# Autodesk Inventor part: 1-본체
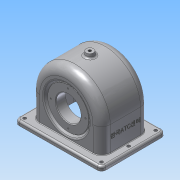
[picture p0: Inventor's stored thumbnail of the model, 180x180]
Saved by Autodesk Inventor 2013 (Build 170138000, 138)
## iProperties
Created: 2015-09
Part Number: 1-본체
Material: 알루미늄 6061
Document SubType Name: Modeling
Designer: Administrator
Mass: 724.051 g
Surface Area: 888.547 cm^2
Volume: 267.177 cm^3
Density: 2.71 g/cm^3
Author: Administrator
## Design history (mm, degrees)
sketch "스케치1"
  geometry: L1 (-45, 70)-(45, 70); L2 (52, 63)-(52, -63); L3 (45, -70)-(-45, -70); L4 (-52, -63)-(-52, 63); A1 r 7 centre (-45, 63) between (-45, 70) and (-52, 63); A2 r 7 centre (45, 63) between (52, 63) and (45, 70); A3 r 7 centre (45, -63) between (45, -70) and (52, -63); A4 r 7 centre (-45, -63) between (-52, -63) and (-45, -70); 6 further points
  constraints: 8 end point, 8 point on circle, 8 tangent, 6 point on line, 4 centre point, 3 equal radius, 2 midpoint, 2 parallel, 1 horizontal, 1 horizontal alignment, 1 perpendicular, 1 vertical alignment
  dimensions: "d0" = 104 distance of point (-52, 70) point (52, 70); "d2" = 140 distance of point (52, 70) point (52, -70); "d3" = 7 radius of A1
extrude "돌출1" new body sketch "스케치1" distance "d4" = 7; taper "d5" = 0 deg
sketch "스케치2"
  geometry: L1 (-63, 0)-(63, 0) reference; L2 (-63, 0)-(-63, 7) reference; L3 (63, 7)-(-63, 7) reference; L4 (63, 0)-(63, 7) reference; L5 (-57, 7)-(-57, 47); L6 (57, 47)-(57, 7); A1 r 57 centre (0, 47) between (57, 47) and (-57, 47); 2 further points
  constraints: 4 end point, 2 point on circle, 2 point on line, 2 tangent, 1 centre point, 1 midpoint, 1 parallel, 1 perpendicular, 1 vertical alignment
  dimensions: "d6" = 57 radius of A1; "d8" = 40 distance from line of A1.centre L3
extrude "돌출2" join sketch "스케치2" stored distance "d9" = 77; taper "d10" = 0 deg
sketch "스케치3"
  geometry: C1 r 31 at (-47, 0); A1 r 57 centre (-47, 0) between (-47, 57) and (-47, -57) reference; 1 further point
  constraints: 1 centre point, 1 coincident
  dimensions: "d11" = 62 diameter of C1
extrude "돌출3" join sketch "스케치3" distance "d12" = 10; taper "d13" = 0 deg
node "작업 평면2"
  node "작업 평면1"
sketch "스케치4"
  geometry: C1 r 6 at (0, 0); 1 further point
  constraints: 1 centre point, 1 coincident
  dimensions: "d15" = 12 diameter of C1
extrude "돌출4" join sketch "스케치4" stored distance "d16" = 5; taper "d17" = 10 deg
sketch "스케치5"
  geometry: L1 (-57, 7)-(57, 7) reference; L2 (-57, 7)-(-57, 47) reference; L3 (57, 47)-(57, 7) reference; L4 (-51, 47)-(-51, 0); L5 (51, 0)-(51, 47); L6 (-51, 0)-(51, 0); A1 r 57 centre (0, 47) between (57, 47) and (-57, 47) reference; A2 r 51 centre (0, 47) between (51, 47) and (-51, 47); 1 further point
  constraints: 6 end point, 2 point on circle, 1 centre point, 1 midpoint, 1 parallel, 1 perpendicular, 1 tangent, 1 other
  dimensions: "d18" = 51 radius of A2
extrude "돌출5" cut sketch "스케치5" stored distance "d20" = 67; taper "d21" = 0 deg
node "작업 평면3"
sketch "스케치7"
  geometry: C1 r 28 at (0, 47); A1 r 57 centre (0, 47) between (57, 47) and (-57, 47) reference; 1 further point
  constraints: 1 centre point, 1 coincident
  dimensions: "d23" = 56 diameter of C1
extrude "돌출6" join sketch "스케치7" stored distance "d24" = 67; taper "d25" = 40 deg
node "작업 평면4"
sketch "스케치8"
  geometry: C1 r 33 at (47, 0); A1 r 57 centre (47, 0) between (47, -57) and (47, 57) reference; 1 further point
  constraints: 1 centre point, 1 coincident
  dimensions: "d27" = 66 diameter of C1
extrude "돌출7" cut sketch "스케치8" distance "d28" = 5; taper "d29" = 40 deg
sketch "스케치9"
  geometry: C1 r 33 at (0, 0) reference; C2 r 33 at (0, 0); 1 further point
  constraints: 1 centre point, 1 coincident
  dimensions: "d30" = 66 diameter of C2
extrude "돌출8" join sketch "스케치9" distance "d32" = 2; taper "d33" = 0 deg
hole "구멍1" diameter "d36" = 40; stored, may be unused: countersink angle "d40" = 90 deg, drill point angle "d42" = 118 deg; dims "d37" = 6, "d38" = 4, "d39" = 2, "d41" = 16, "d43" = 10, "d44" = 10
hole "구멍2" diameter "d47" = 40; stored, may be unused: countersink angle "d51" = 90 deg, drill point angle "d53" = 118 deg; dims "d48" = 6, "d49" = 4, "d50" = 2, "d52" = 15, "d54" = 10, "d55" = 10
sketch "스케치11"
  geometry: C1 r 33 at (0, 0) reference; A1 r 28 centre (0, 0) between (28, 0) and (0, 28); 3 further points
  constraints: 4 point on circle, 2 horizontal alignment, 2 vertical alignment, 1 centre point, 1 coincident
  dimensions: "d56" = 56 diameter of A1
hole "구멍3" sketch "스케치11" at (28, 0), (0, 28), (-28, 0), (0, -28) diameter "d57" = 2.459; stored, may be unused: countersink angle "d61" = 90 deg, drill point angle "d63" = 118 deg; dims "d58" = 7, "d59" = 4, "d60" = 2, "d62" = 9
sketch "스케치12"
  geometry: C1 r 31 at (0, 0) reference; A1 r 24 centre (0, 0) between (-24, 0) and (0, 24); 3 further points
  constraints: 4 point on circle, 2 horizontal alignment, 2 vertical alignment, 1 centre point, 1 coincident
  dimensions: "d64" = 48 diameter of A1
hole "구멍4" sketch "스케치12" at (-24, 0), (0, 24), (24, 0), (0, -24) diameter "d65" = 2.459; stored, may be unused: countersink angle "d69" = 90 deg, drill point angle "d71" = 118 deg; dims "d66" = 6, "d67" = 4, "d68" = 2, "d70" = 8
hole "구멍5" diameter "d74" = 4.459; stored, may be unused: countersink angle "d78" = 90 deg, drill point angle "d80" = 0 deg; dims "d72" = 10, "d73" = 10, "d75" = 20, "d76" = 4, "d77" = 2, "d79" = 20
sketch "스케치13"
  geometry: L1 (-44, 62)-(44, 62); L2 (44, 62)-(44, -62); L3 (44, -62)-(-44, -62); L4 (-44, -62)-(-44, 62); L5 (-52, -63)-(-52, 63) reference; 9 further points
  constraints: 8 end point, 5 coincident, 3 midpoint, 2 parallel, 1 horizontal, 1 horizontal alignment, 1 perpendicular, 1 vertical alignment
  dimensions: "d81" = 124 distance of L1.end L2.end; "d83" = 8 distance between parallel lines of L5 L4
hole "구멍6" sketch "스케치13" at (-44, 62), (0, 62), (44, 62), (-44, -62), (0, -62), (44, -62) diameter "d84" = 5; stored, may be unused: countersink angle "d88" = 90 deg, drill point angle "d90" = 0 deg; dims "d85" = 20, "d86" = 4, "d87" = 2, "d89" = 20
chamfer "모따기1" distance "d91" = 1; stored, may be unused: second distance "d92" = 2, angle "d93" = 45 deg
fillet "모깎기1" dims "d94" = 14
fillet "모깎기2" dims "d95" = 9
fillet "모깎기3" dims "d96" = 1
fillet "모깎기4" dims "d97" = 3
fillet "모깎기5" dims "d98" = 0.5
fillet "모깎기6" dims "d99" = 3
fillet "모깎기7" dims "d100" = 3
fillet "모깎기8" dims "d101" = 3
fillet "모깎기9" dims "d102" = 3
sketch "스케치14"
  geometry: L1 (-0.387, -13.398)-(49.387, -13.398); L2 (49.387, -13.398)-(49.387, -20.602); L3 (49.387, -20.602)-(-0.387, -20.602); L4 (-0.387, -20.602)-(-0.387, -13.398); L5 (-14, 0)-(-14, -39) reference; L6 (-27.5, -47)-(-20.5, -47) reference; 4 further points
  constraints: 2 midpoint, 1 horizontal alignment, 1 parallel, 1 vertical alignment, 2 other
  dimensions: "d103" = 38.5 distance from line of point (24.5, -17) L5; "d104" = 30 distance from line of point (24.5, -17) L6; "d105" = 63.38738 distance between parallel lines of L2 L5; "d106" = 33.60244 distance between parallel lines of L1 L6
feature "엠보싱1" sketch "스케치14" dims "d0" = 104, "d2" = 140, "d3" = 7, "d6" = 57, "d8" = 40, "d107" = 0.5, "d108" = 0
node "솔리드1"
node "투영된 루프1"
node "투영된 루프2"
other parameters: "d14" = 6, "d22" = -19, "d26" = -5
